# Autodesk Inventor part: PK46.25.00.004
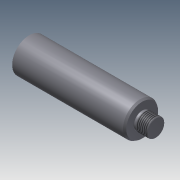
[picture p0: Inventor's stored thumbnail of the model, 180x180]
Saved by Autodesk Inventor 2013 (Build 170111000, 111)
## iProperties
Created: 2005-05
Part Number: PK46.25.00.004
Material: Steel, Mild
Document SubType Name: Modeling
Designer: PVitaliy
Manufacturer: Standard
Standards Organization: Custom
Density: 7.86 g/cm^3
Author: PVitaliy
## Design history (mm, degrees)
sketch "Эскиз2"
  geometry: L1 (0, 0)-(95.139, 0); L2 (0, 0)-(0, 25.897); L3 (0, 25.897)-(13, 35); L4 (13, 35)-(15, 35); L5 (15, 35)-(15, 50); L6 (15, 50)-(339, 50); L7 (339, 50)-(345, 46.536); L8 (345, 46.536)-(345, 24.5); L9 (345, 24.5)-(351, 24.5); L10 (351, 24.5)-(352.5, 26); L11 (352.5, 26)-(385, 26); L12 (385, 26)-(385, 0); L13 (385, 0)-(0, 0)
  constraints: 26 end point, 6 horizontal, 4 vertical, 1 other
  dimensions: "d0" = 70 diameter of L4 L1; "d1" = 35 deg angle of L3 L4; "d2" = 15 distance between parallel lines of L5 L2; "d3" = 2 distance of L3.end L4.end; "d4" = 100 diameter of L6 L1; "d5" = 330 distance between parallel lines of L8 L5; "d6" = 30 deg angle of L6 L7; "d7" = 6 horizontal distance of L6.end L7.end; "d8" = 385 distance between parallel lines of L12 L2; "d9" = 52 diameter of L11 L1; "d10" = 6 distance of L8.end L9.end; "d11" = 49 diameter of L9 L1; "d12" = 45 deg angle of L10 L9
revolve "Вращение1" sketch "Эскиз2" stored, may be unused: angle "d13" = 90 deg
feature "Резьба1" dims "d14" = 10, "d15" = 0
chamfer "Фаска1" distance "d16" = 1.6; stored, may be unused: second distance "d17" = 2, angle "d18" = 45 deg
fillet "Сопряжение1" dims "d19" = 1, "d20" = 0.5
body "Solid1"
